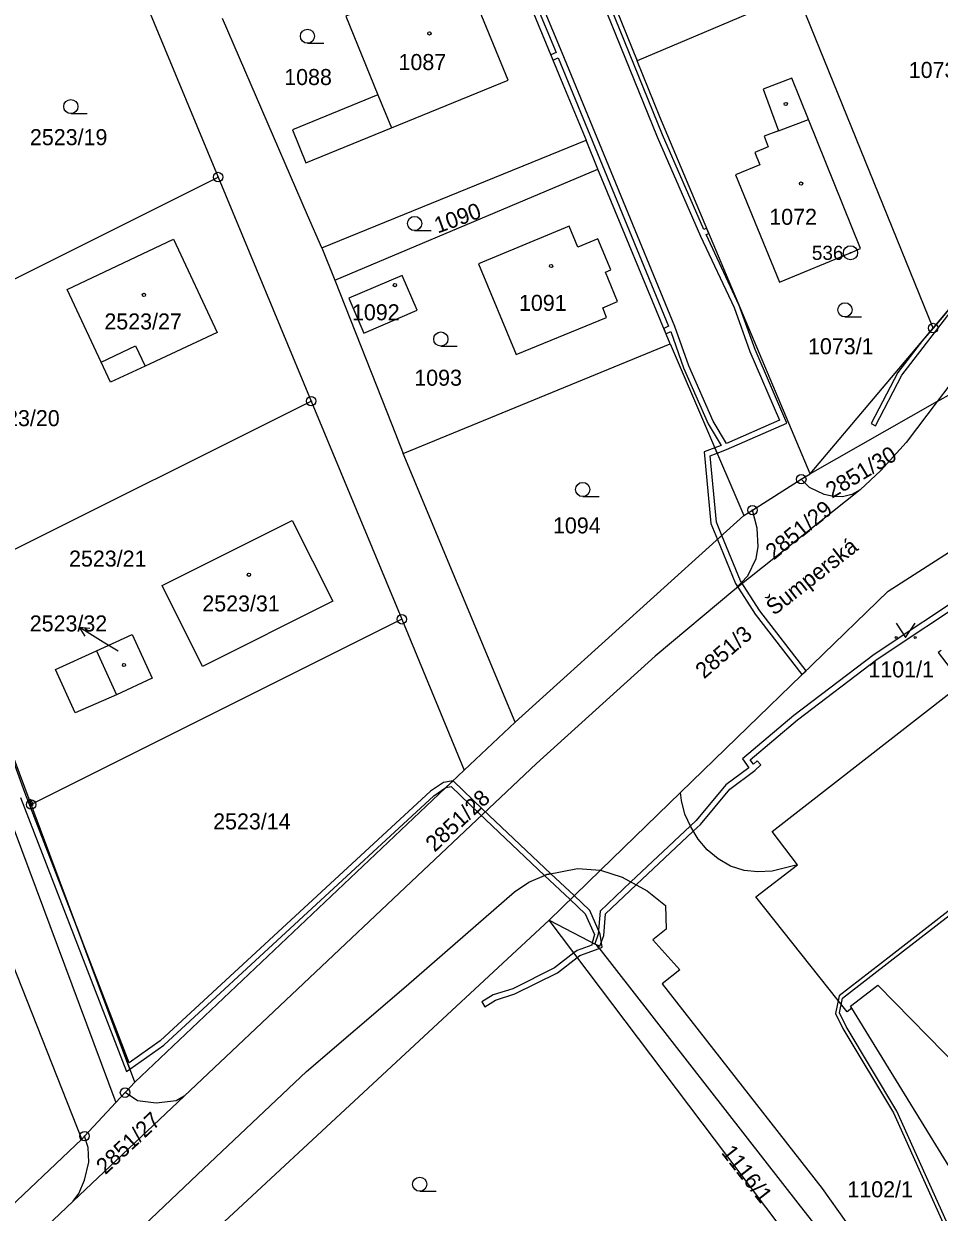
# Model space of a CAD drawing. Extents: x -562167 to -556918, y -1077891 to -1070763.
# Drawn here: x -559331.5 to -559234.3, y -1074790.1 to -1074664.1 of the extents above; entities that cross this region are included whole.
import ezdxf

# ---------------------------------------------------------------- set-up
doc = ezdxf.new("R2010")
doc.units = 0
for name, color, linetype in [('Hranice parcel', 7, 'Continuous'), ('Parcelní čísla', 7, 'Continuous'), ('Pop  PČ popisy', 7, 'Continuous'), ('Vnitřní kresba', 7, 'Continuous'), ('Věcná břemena k části', 7, 'Continuous'), ('Značky bodu BP', 7, 'Continuous'), ('Značky budov', 7, 'Continuous'), ('Značky kultur', 7, 'Continuous')]:
    doc.layers.add(name, color=color, linetype=linetype)

msp = doc.modelspace()

# ---------------------------------------------------------------- linework, layer by layer
at = {"layer": 'Hranice parcel'}
for p, q in [((-559320.83, -1074656.31), (-559310.86, -1074680.32)), ((-559269.18, -1074661.07), (-559266.4, -1074667.98)), ((-559299.83, -1074687.83), (-559271.79, -1074676.4)), ((-559270.55, -1074679.47), (-559271.79, -1074676.4)), ((-559298.47, -1074691.27), (-559270.55, -1074679.47)), ((-559262.89, -1074698.01), (-559270.55, -1074679.47)), ((-559348.96, -1074699.36), (-559310.86, -1074680.32)), ((-559310.86, -1074680.32), (-559300.98, -1074704.09)), ((-559299.83, -1074687.83), (-559298.47, -1074691.27)), ((-559234.57, -1074704.15), (-559216.08, -1074693.66)), ((-559248.04, -1074711.8), (-559234.98, -1074696.34)), ((-559291.21, -1074709.64), (-559262.89, -1074698.01)), ((-559262.89, -1074698.01), (-559255.06, -1074716.22)), ((-559339.54, -1074723.36), (-559300.98, -1074704.09)), ((-559300.98, -1074704.09), (-559291.37, -1074727.24)), ((-559234.57, -1074704.15), (-559248.04, -1074711.8)), ((-559279.35, -1074738.14), (-559291.21, -1074709.64)), ((-559254.15, -1074715.65), (-559248.97, -1074712.38)), ((-559248.97, -1074712.38), (-559248.04, -1074711.8)), ((-559242.73, -1074713.5), (-559256.02, -1074724.09)), ((-559279.35, -1074738.14), (-559255.06, -1074716.22)), ((-559255.06, -1074716.22), (-559254.15, -1074715.65)), ((-559291.37, -1074727.24), (-559330.7, -1074746.89)), ((-559291.37, -1074727.24), (-559284.73, -1074743.24)), ((-559284.73, -1074743.24), (-559279.35, -1074738.14)), ((-559319.7, -1074776.35), (-559284.73, -1074743.24)), ((-559270.29, -1074753.86), (-559261.78, -1074745.6)), ((-559319.7, -1074776.35), (-559330.7, -1074746.89)), ((-559325.32, -1074782.39), (-559337.91, -1074750.54)), ((-559275.74, -1074759.15), (-559270.29, -1074753.86)), ((-559275.74, -1074759.15), (-559318.33, -1074798.68)), ((-559320.73, -1074777.46), (-559319.7, -1074776.35)), ((-559314.44, -1074777.83), (-559326.23, -1074788.98)), ((-559321.71, -1074778.51), (-559320.73, -1074777.46)), ((-559325.02, -1074782.07), (-559321.71, -1074778.51)), ((-559325.32, -1074782.39), (-559325.02, -1074782.07)), ((-559360.92, -1074816.13), (-559325.32, -1074782.39)), ((-559326.23, -1074788.98), (-559367.16, -1074827.67))]:
    msp.add_line(p, q, dxfattribs=at)
for points in [[(-559148.84, -1074568.33), (-559153.15, -1074571.45), (-559157.45, -1074575.18), (-559162.93, -1074580.49), (-559167.98, -1074586.26), (-559174.83, -1074594.73), (-559181.81, -1074603.66), (-559187.37, -1074611.26), (-559193.04, -1074619.74), (-559198.16, -1074628.13), (-559203.1, -1074636.86), (-559207.67, -1074645.75), (-559211.93, -1074654.95), (-559221.53, -1074677.33), (-559228.12, -1074692.82), (-559231.29, -1074699.08), (-559233.33, -1074702.52), (-559234.57, -1074704.15)], [(-559281.95, -1074651.88), (-559274.28, -1074670.46), (-559271.79, -1074676.4)], [(-559365.76, -1074657.82), (-559355.68, -1074686.11), (-559342.59, -1074724.17), (-559336.43, -1074739.14), (-559321.71, -1074778.51)], [(-559280.07, -1074670.06), (-559284.93, -1074658.24), (-559297.29, -1074663.27), (-559293.89, -1074671.6), (-559302.97, -1074675.3), (-559301.53, -1074678.82), (-559292.45, -1074675.11), (-559280.07, -1074670.06)], [(-559234.98, -1074696.34), (-559249.41, -1074660.77), (-559266.4, -1074667.98)], [(-559299.83, -1074687.83), (-559301.37, -1074684.38), (-559310.37, -1074663.49)], [(-559248.04, -1074711.8), (-559264, -1074673.94), (-559266.4, -1074667.98)], [(-559251.38, -1074675.41), (-559252.9, -1074675.99), (-559252.48, -1074677.12), (-559253.92, -1074677.72), (-559253.37, -1074679.04), (-559255.95, -1074680.1), (-559251.27, -1074691.48), (-559243.75, -1074688.36), (-559242.69, -1074687.89), (-559248.21, -1074674.22), (-559249.99, -1074669.82), (-559253.02, -1074671), (-559251.38, -1074675.41)], [(-559234.98, -1074696.34), (-559231.08, -1074691.72), (-559222.06, -1074669.47)], [(-559269.65, -1074695.22), (-559270.02, -1074694.18), (-559268.46, -1074693.53), (-559269.76, -1074690.41), (-559269.19, -1074690.17), (-559270.57, -1074686.87), (-559272.69, -1074687.76), (-559273.62, -1074685.53), (-559283.23, -1074689.52), (-559279.22, -1074699.14), (-559269.65, -1074695.22)], [(-559315.58, -1074686.91), (-559310.94, -1074696.8), (-559318.61, -1074700.39), (-559322.26, -1074702.1), (-559323.27, -1074699.95), (-559326.88, -1074692.25), (-559315.58, -1074686.91)], [(-559298.47, -1074691.27), (-559292.43, -1074706.57), (-559291.21, -1074709.64)], [(-559295.4, -1074696.9), (-559289.73, -1074694.43), (-559291.33, -1074690.78), (-559296.98, -1074693.16), (-559295.4, -1074696.9)], [(-559234.57, -1074704.15), (-559237.84, -1074708.48), (-559240.54, -1074711.45), (-559242.73, -1074713.5)], [(-559261.78, -1074745.6), (-559255.82, -1074739.81), (-559239.75, -1074724.26), (-559225.47, -1074715.1), (-559219.56, -1074713.57), (-559216.17, -1074712.7), (-559196.74, -1074707.68)], [(-559242.73, -1074713.5), (-559243.61, -1074714.01), (-559244.59, -1074714.25), (-559245.57, -1074714.21), (-559246.56, -1074714), (-559248.11, -1074713.24), (-559248.97, -1074712.38)], [(-559256.02, -1074724.09), (-559254.66, -1074722.63), (-559253.77, -1074720.8), (-559253.54, -1074719.56), (-559253.66, -1074717.57), (-559254.15, -1074715.65)], [(-559298.69, -1074725.33), (-559312.52, -1074732.25), (-559316.78, -1074723.65), (-559302.98, -1074716.75), (-559298.69, -1074725.33)], [(-559249.37, -1074753.28), (-559252.07, -1074749.77), (-559220.36, -1074725.06), (-559218.04, -1074723.54), (-559215.62, -1074722.22), (-559213.12, -1074721.08), (-559210.55, -1074720.09), (-559207.87, -1074719.33), (-559205.15, -1074718.9), (-559202.39, -1074718.77), (-559199.55, -1074718.85), (-559199.06, -1074720.72), (-559198.32, -1074722.58), (-559197.76, -1074723.41), (-559196.19, -1074724.66), (-559194.35, -1074725.42), (-559192.37, -1074725.69), (-559185.09, -1074725.84)], [(-559330.7, -1074746.89), (-559338.36, -1074726.36), (-559339.54, -1074723.36)], [(-559256.02, -1074724.09), (-559264.47, -1074731.14), (-559277.08, -1074742.54), (-559314.44, -1074777.83)], [(-559326.02, -1074737.16), (-559328.1, -1074732.55), (-559323.77, -1074730.59), (-559319.97, -1074728.86), (-559317.85, -1074733.5), (-559321.62, -1074735.24), (-559326.02, -1074737.16)], [(-559249.37, -1074753.28), (-559252.08, -1074753.95), (-559253.59, -1074754.03), (-559255.05, -1074753.89), (-559256.5, -1074753.44), (-559257.8, -1074752.66), (-559258.95, -1074751.71), (-559259.92, -1074750.55), (-559260.71, -1074749.27), (-559261.32, -1074747.9), (-559261.7, -1074746.45), (-559261.78, -1074745.6)], [(-559417.52, -1074892.59), (-559418.01, -1074891.41), (-559418.25, -1074888.35), (-559417.85, -1074886.61), (-559416.98, -1074884.81), (-559415.75, -1074883.29), (-559391.59, -1074860.49), (-559364.46, -1074834.85), (-559336.5, -1074808.4), (-559313.05, -1074786.15), (-559301.46, -1074775.22), (-559290.89, -1074766.15), (-559279.41, -1074756.14), (-559277.89, -1074755.12), (-559275.98, -1074754.32), (-559272.73, -1074753.67), (-559270.29, -1074753.86)], [(-559270.29, -1074753.86), (-559267.97, -1074754.6), (-559265.33, -1074756.05), (-559263.39, -1074757.62), (-559263.31, -1074760.13), (-559264.74, -1074761.26), (-559261.85, -1074764.44), (-559263.75, -1074765.91), (-559246.75, -1074787.62), (-559244.26, -1074791.18)], [(-559243.62, -1074768.5), (-559244.11, -1074768.88), (-559253.81, -1074756.69), (-559249.37, -1074753.28)], [(-559275.74, -1074759.15), (-559270.71, -1074761.78), (-559249.08, -1074789.5), (-559246.46, -1074792.82), (-559243.09, -1074797.16), (-559228.96, -1074815.31)], [(-559259.35, -1074806.49), (-559251.44, -1074791.34), (-559275.74, -1074759.15)], [(-559243.62, -1074768.5), (-559243.75, -1074768.29), (-559240.86, -1074766.07), (-559232.06, -1074775.04), (-559226.42, -1074770.66)], [(-559220.12, -1074809.15), (-559232.46, -1074793.37), (-559229.67, -1074791.17), (-559243.62, -1074768.5)], [(-559314.44, -1074777.83), (-559315.32, -1074778.33), (-559317.42, -1074778.59), (-559319.41, -1074778.31), (-559320.73, -1074777.46)], [(-559326.23, -1074788.98), (-559325.63, -1074788.15), (-559325.03, -1074786.76), (-559324.57, -1074784.83), (-559324.65, -1074783.26), (-559325.02, -1074782.07)]]:
    msp.add_lwpolyline(points, dxfattribs=at)
at = {"layer": 'Pop  PČ popisy'}
for p, q in [((-559323.05, -1074729.65), (-559325.59, -1074728.06)), ((-559325.59, -1074728.06), (-559324.48, -1074728.17)), ((-559325.59, -1074728.06), (-559325.01, -1074729.02)), ((-559321.45, -1074730.63), (-559323.05, -1074729.65))]:
    msp.add_line(p, q, dxfattribs=at)
at = {"layer": 'Vnitřní kresba'}
for p, q in [((-559293.89, -1074671.6), (-559292.45, -1074675.11)), ((-559251.38, -1074675.41), (-559248.21, -1074674.22)), ((-559323.27, -1074699.95), (-559319.63, -1074698.22)), ((-559319.63, -1074698.22), (-559318.61, -1074700.39)), ((-559323.77, -1074730.59), (-559321.62, -1074735.24))]:
    msp.add_line(p, q, dxfattribs=at)
at = {"layer": 'Věcná břemena k části'}
for points in [[(-559284.15, -1074645.16), (-559275, -1074667.11), (-559275.56, -1074667.37), (-559275.33, -1074667.92), (-559274.77, -1074667.67), (-559263.05, -1074696.13), (-559263.56, -1074696.38), (-559263.33, -1074696.94), (-559262.83, -1074696.69), (-559261.46, -1074700.57), (-559258.86, -1074706.5)], [(-559272.04, -1074656.86), (-559264.25, -1074676.07), (-559259.67, -1074686.58), (-559256.09, -1074694.16), (-559254.42, -1074698.84), (-559251.29, -1074706.12), (-559256.91, -1074708.58), (-559258.33, -1074706.22), (-559260.9, -1074700.35), (-559262.38, -1074696.16), (-559274.33, -1074667.15), (-559283.6, -1074644.92)], [(-559258.86, -1074706.5), (-559257.48, -1074708.81), (-559258.14, -1074709.06), (-559257.9, -1074709.61), (-559256.92, -1074709.24), (-559250.5, -1074706.43), (-559253.86, -1074698.62), (-559255.57, -1074693.94), (-559259.08, -1074686.43), (-559258.78, -1074686.31), (-559259.02, -1074685.76), (-559259.32, -1074685.88), (-559263.7, -1074675.84), (-559271.24, -1074657.23)], [(-559230.8, -1074724.03), (-559241.25, -1074730.99), (-559249.76, -1074737.46), (-559255.22, -1074742.04), (-559254.53, -1074743), (-559256.98, -1074744.81), (-559260.12, -1074748.58), (-559260.75, -1074749.18), (-559267.05, -1074755.11), (-559270.33, -1074758.2), (-559270.51, -1074760.66), (-559270.89, -1074761.68), (-559270.34, -1074761.91), (-559269.91, -1074760.8), (-559269.75, -1074758.48), (-559266.49, -1074755.41), (-559260.44, -1074749.71), (-559259.68, -1074749), (-559256.56, -1074745.25), (-559253.92, -1074743.29), (-559253.26, -1074742.69), (-559253.66, -1074742.25), (-559254.06, -1074742.61), (-559254.4, -1074742.14), (-559249.38, -1074737.92), (-559240.91, -1074731.47), (-559230.48, -1074724.53)], [(-559331.81, -1074746.13), (-559320.56, -1074775.21), (-559320.22, -1074774.97), (-559325.87, -1074759.81), (-559331.36, -1074745.63), (-559338.36, -1074726.36)], [(-559234.12, -1074730.54), (-559234.44, -1074730.78), (-559224.65, -1074743.55)], [(-559231.83, -1074757.01), (-559239.46, -1074762.93), (-559244.95, -1074767.2), (-559245.35, -1074769.05), (-559244.58, -1074770.65), (-559239.18, -1074779.6), (-559232.65, -1074794.15)], [(-559232.29, -1074793.97), (-559238.82, -1074779.42), (-559244.22, -1074770.45), (-559244.93, -1074768.99), (-559244.59, -1074767.42), (-559239.21, -1074763.25), (-559231.74, -1074757.45)]]:
    msp.add_lwpolyline(points, dxfattribs=at)
for points in [[(-559221.61, -1074668.54), (-559222.15, -1074671.44), (-559224.09, -1074674.49), (-559231.08, -1074691.72), (-559234.98, -1074696.34), (-559236.11, -1074697.67), (-559238.72, -1074701.06), (-559241.55, -1074706.48), (-559241.1, -1074706.71), (-559238.3, -1074701.34), (-559232.46, -1074693.77), (-559230.56, -1074691.86), (-559230.12, -1074690.13), (-559227.35, -1074683.3), (-559223.63, -1074674.69), (-559221.67, -1074671.62), (-559221.01, -1074668.03), (-559220.23, -1074665.69)], [(-559257.88, -1074718.76), (-559257.4, -1074718.34), (-559257.98, -1074716.94), (-559258.63, -1074709.89), (-559257.9, -1074709.61), (-559258.14, -1074709.06), (-559259.27, -1074709.49), (-559258.57, -1074717.08)], [(-559253.86, -1074726.7), (-559248.9, -1074733.11), (-559248.47, -1074732.69), (-559253.37, -1074726.35), (-559255.43, -1074723.16), (-559257.4, -1074718.34), (-559257.88, -1074718.76), (-559255.96, -1074723.44)], [(-559325.87, -1074759.81), (-559320.22, -1074774.97), (-559316.63, -1074772.42), (-559287.96, -1074745.96), (-559286.7, -1074745.1), (-559285.91, -1074744.36), (-559286.93, -1074744.54), (-559288.33, -1074745.49), (-559317.01, -1074771.96), (-559320.28, -1074774.28)], [(-559285.91, -1074744.36), (-559286.7, -1074745.1), (-559286.13, -1074744.98), (-559283.16, -1074747.86), (-559276.22, -1074754.42), (-559275.98, -1074754.32), (-559275.54, -1074754.23), (-559282.75, -1074747.43)], [(-559330.67, -1074746.98), (-559330.7, -1074746.89), (-559330.88, -1074746.41), (-559331.03, -1074746.48), (-559330.81, -1074747.04)], [(-559330.7, -1074746.89), (-559330.53, -1074746.81), (-559330.73, -1074746.35), (-559330.88, -1074746.41)], [(-559330.7, -1074746.89), (-559330.67, -1074746.98), (-559330.49, -1074746.9), (-559330.53, -1074746.81)], [(-559273.5, -1074756.98), (-559271.91, -1074758.48), (-559270.93, -1074760.69), (-559271.15, -1074761.55), (-559270.71, -1074761.78), (-559270.42, -1074762.15), (-559270.11, -1074762.04), (-559270.3, -1074760.63), (-559271.42, -1074758.12), (-559273.07, -1074756.56), (-559275.54, -1074754.23), (-559275.98, -1074754.32), (-559276.22, -1074754.42)], [(-559272.74, -1074763.12), (-559272.48, -1074762.91), (-559270.42, -1074762.15), (-559270.71, -1074761.78), (-559271.15, -1074761.55), (-559271.21, -1074761.81), (-559272.77, -1074762.38), (-559273.11, -1074762.64), (-559275.15, -1074764.22), (-559279.58, -1074766.43), (-559281.67, -1074767.08), (-559282.88, -1074767.84), (-559282.56, -1074768.35), (-559281.41, -1074767.63), (-559279.36, -1074766.99), (-559274.83, -1074764.73)]]:
    msp.add_lwpolyline(points, close=True, dxfattribs=at)
at = {"layer": 'Značky bodu BP'}
for centre, radius in [((-559310.86, -1074680.32), 0.5), ((-559310.86, -1074680.32), 0.0303), ((-559243.75, -1074688.36), 0.75), ((-559243.75, -1074688.36), 0.03), ((-559234.98, -1074696.34), 0.5), ((-559234.98, -1074696.34), 0.0303), ((-559300.98, -1074704.09), 0.5), ((-559300.98, -1074704.09), 0.0303), ((-559248.97, -1074712.38), 0.5), ((-559248.97, -1074712.38), 0.0303), ((-559254.15, -1074715.65), 0.5), ((-559254.15, -1074715.65), 0.0303), ((-559291.37, -1074727.24), 0.5), ((-559291.37, -1074727.24), 0.0303), ((-559330.7, -1074746.89), 0.5), ((-559330.7, -1074746.89), 0.0303), ((-559320.73, -1074777.46), 0.5), ((-559320.73, -1074777.46), 0.0303), ((-559325.02, -1074782.07), 0.5), ((-559325.02, -1074782.07), 0.0303)]:
    msp.add_circle(centre, radius, dxfattribs=at)
at = {"layer": 'Značky budov'}
for centre in [(-559288.43, -1074665.08), (-559250.62, -1074672.57), (-559248.99, -1074681.01), (-559275.52, -1074689.76), (-559292.1, -1074691.79), (-559318.72, -1074692.82), (-559307.58, -1074722.51), (-559320.84, -1074732.09)]:
    msp.add_circle(centre, 0.175, dxfattribs=at)
at = {"layer": 'Značky kultur'}
for p, q in [((-559301.37, -1074666.13), (-559299.62, -1074666.13)), ((-559326.48, -1074673.59), (-559324.73, -1074673.59)), ((-559290, -1074686), (-559288.25, -1074686)), ((-559244.34, -1074695.16), (-559242.59, -1074695.16)), ((-559287.22, -1074698.26), (-559285.47, -1074698.26)), ((-559272.17, -1074714.22), (-559270.42, -1074714.22)), ((-559289.46, -1074787.92), (-559287.71, -1074787.92))]:
    msp.add_line(p, q, dxfattribs=at)
msp.add_lwpolyline([(-559238.9, -1074727.66), (-559237.9, -1074729.16), (-559236.9, -1074727.66)], dxfattribs=at)
for centre, radius in [((-559301.37, -1074665.38), 0.75), ((-559326.48, -1074672.84), 0.75), ((-559290, -1074685.25), 0.75), ((-559244.34, -1074694.41), 0.75), ((-559287.22, -1074697.51), 0.75), ((-559272.17, -1074713.47), 0.75), ((-559238.9, -1074729.16), 0.1), ((-559236.9, -1074729.16), 0.1), ((-559289.46, -1074787.17), 0.75)]:
    msp.add_circle(centre, radius, dxfattribs=at)

# ---------------------------------------------------------------- texts
at = {"layer": 'Parcelní čísla'}
for s, p in [('1087', (-559291.71, -1074668.97)), ('1073/2', (-559237.57, -1074669.81)), ('1088', (-559303.84, -1074670.56)), ('2523/19', (-559330.82, -1074676.94)), ('1072', (-559252.37, -1074685.39)), ('1092', (-559296.65, -1074695.52)), ('1091', (-559278.93, -1074694.52)), ('2523/27', (-559322.92, -1074696.49)), ('1073/1', (-559248.26, -1074699.12)), ('1093', (-559290.04, -1074702.46)), ('2523/20', (-559335.88, -1074706.75)), ('1094', (-559275.32, -1074718.13)), ('2523/21', (-559326.67, -1074721.65)), ('2523/31', (-559312.53, -1074726.41)), ('2523/32', (-559330.84, -1074728.53)), ('1101/1', (-559241.85, -1074733.4)), ('2523/14', (-559311.38, -1074749.53)), ('1102/1', (-559244.08, -1074788.56))]:
    msp.add_text(s, height=1.7, dxfattribs=at).set_placement(p)
for s, rotation, p in [('1090', 20, (-559287.54, -1074686.32)), ('2851/30', 31, (-559245.72, -1074714.46)), ('2851/29', 39, (-559251.9, -1074721.01)), ('2851/3', 41, (-559259.29, -1074733.63)), ('2851/28', 43, (-559287.87, -1074752.01)), ('2851/27', 43, (-559322.82, -1074786.22)), ('1116/1', 308, (-559257.53, -1074783.84))]:
    msp.add_text(s, height=1.7, rotation=rotation, dxfattribs=at).set_placement(p)
at = {"layer": 'Pop  PČ popisy'}
msp.add_text('Šumperská', height=1.7, rotation=38, dxfattribs=at).set_placement((-559251.87, -1074726.9))
at = {"layer": 'Značky bodu BP'}
msp.add_text('536', height=1.5, dxfattribs=at).set_placement((-559247.85, -1074689.11))

doc.saveas('drawing.dxf')
